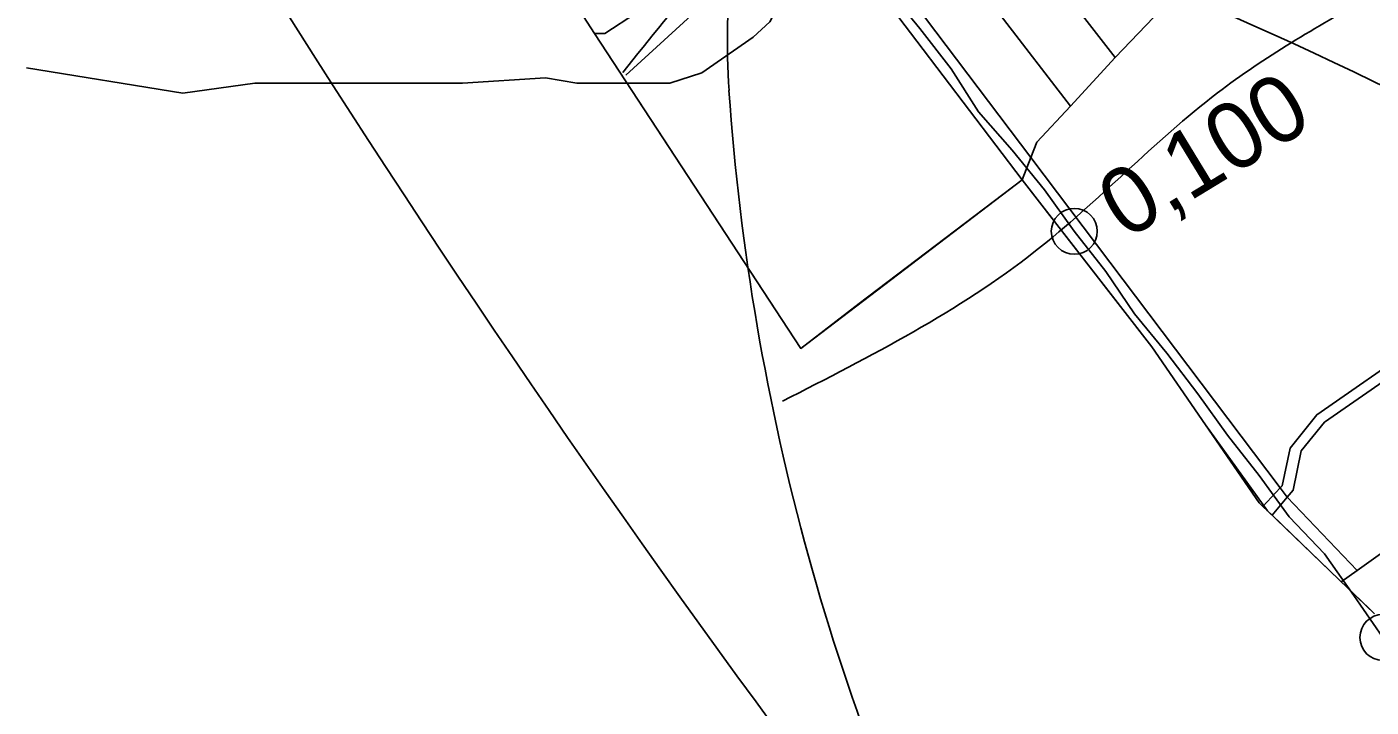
# Model space of a CAD drawing. Extents: x -510989 to -501240, y -1184665 to -1176089.
# Drawn here: x -505400.5 to -505137.3, y -1182850.2 to -1182717 of the extents above; entities that cross this region are included whole.
import ezdxf

# ---------------------------------------------------------------- set-up
doc = ezdxf.new("R2010")
doc.units = 0
for name, color, linetype in [('NAVRH_revitalizace_toku', 7, 'Continuous'), ('NAVRH_rozvodnice', 7, 'Continuous'), ('orna_puda', 7, 'Continuous'), ('ostatni_plocha_x_silnice', 7, 'Continuous'), ('popis', 7, 'Continuous'), ('STAV_povodi', 7, 'Continuous'), ('STAV_zaplavove_uzemi', 7, 'Continuous'), ('trasovani_toku', 7, 'Continuous'), ('trvaly_travni_porost', 7, 'Continuous'), ('vodni_plocha_x_vodni_tok_v_koryt_prir_n_upr', 7, 'Continuous'), ('vrstevnice_02', 7, 'Continuous')]:
    doc.layers.add(name, color=color, linetype=linetype)

msp = doc.modelspace()

# ---------------------------------------------------------------- linework, layer by layer
at = {"layer": 'NAVRH_revitalizace_toku'}
msp.add_lwpolyline([(-505283.2, -1182726.47), (-505221.54, -1182670.07), (-505202.54, -1182651.66), (-505180.34, -1182644.65), (-505164.26, -1182628.87), (-505157.25, -1182622.73), (-505143.22, -1182616.3), (-505134.75, -1182614.84), (-505111.96, -1182609.29), (-505091.21, -1182601.11), (-505056.43, -1182579.77), (-505023.12, -1182558.15), (-505007.92, -1182543.25), (-505004.12, -1182535.35), (-504999.17, -1182521.37), (-504988.56, -1182507.87), (-504967.99, -1182486.66), (-504957.7, -1182478.94), (-504947.42, -1182468.01), (-504933.59, -1182458.37), (-504921.38, -1182450.01)], dxfattribs=at)
at = {"layer": 'NAVRH_rozvodnice'}
for centre, radius, start, end in [((-503349.55, -1181451.68), 2365.2, 210.66565, 230.3961), ((-505125.66, -1182720), 137.67, 162.3818, 183.9514), ((-505444.54, -1183359.44), 702.72, 47.17982, 69.65509), ((-504801.14, -1182697.59), 462.97, 183.9514, 206.882)]:
    msp.add_arc(centre, radius, start, end, dxfattribs=at)
at = {"layer": 'orna_puda'}
for points in [[(-505231.63, -1182667.65), (-505226.84, -1182655.02), (-505192.37, -1182699.02), (-505179.82, -1182715.12), (-505187.44, -1182722.98), (-505200.69, -1182705.9)], [(-505241.82, -1182674.43), (-505231.63, -1182667.65), (-505200.69, -1182705.9), (-505187.44, -1182722.98), (-505196.15, -1182732.5), (-505209.95, -1182714.66), (-505211.47, -1182712.73)], [(-505250.53, -1182680.83), (-505241.82, -1182674.43), (-505211.47, -1182712.73), (-505209.95, -1182714.66), (-505196.15, -1182732.5), (-505202.73, -1182739.56), (-505203.93, -1182742.58), (-505222.49, -1182717.98)], [(-505156.25, -1182694.93), (-505150.23, -1182691.81), (-505144.19, -1182698.42), (-505095.58, -1182752.22), (-505092.58, -1182755.01), (-505109.05, -1182765.57), (-505128.01, -1182779.16), (-505147.95, -1182792.96), (-505153.14, -1182799.48), (-505154.69, -1182806.86), (-505155.1, -1182807.3), (-505203.93, -1182742.58), (-505202.73, -1182739.56), (-505196.15, -1182732.5), (-505187.44, -1182722.98), (-505179.82, -1182715.12), (-505171.72, -1182706.71), (-505163.37, -1182699.78)]]:
    msp.add_lwpolyline(points, close=True, dxfattribs=at)
for points in [[(-505091.34, -1182756.24), (-505146.42, -1182794.45), (-505150.98, -1182800.01), (-505152.59, -1182807.74), (-505153.74, -1182809.11), (-505155.1, -1182807.3), (-505154.69, -1182806.86), (-505153.14, -1182799.48), (-505147.95, -1182792.96), (-505128.01, -1182779.16)], [(-505135, -1182819.86), (-505140.03, -1182823.47), (-505153.74, -1182809.11), (-505152.59, -1182807.74), (-505150.98, -1182800.01), (-505146.42, -1182794.45), (-505091.34, -1182756.24)]]:
    msp.add_lwpolyline(points, dxfattribs=at)
at = {"layer": 'ostatni_plocha_x_silnice'}
msp.add_lwpolyline([(-505137.06, -1182831.56), (-505137.71, -1182830.93), (-505142.18, -1182826.63), (-505143.15, -1182825.7), (-505140.03, -1182823.47), (-505135, -1182819.86)], dxfattribs=at)
at = {"layer": 'popis'}
msp.add_lwpolyline([(-505136.66, -1182831.95), (-505143.65, -1182825.21), (-505157.59, -1182811.77), (-505169.71, -1182794.94), (-505180.22, -1182779.67), (-505192.93, -1182763.3), (-505205.65, -1182746.93), (-505248.97, -1182779.98), (-505289.32, -1182718.3), (-505291.51, -1182714.95), (-505297.03, -1182708.17), (-505302.52, -1182701.43), (-505318.05, -1182675.76), (-505333.58, -1182650.08), (-505360.57, -1182611.94), (-505382.19, -1182577), (-505390.4, -1182557.12), (-505398.6, -1182537.25), (-505408.11, -1182520.53), (-505418.12, -1182507.31), (-505446.34, -1182476.48), (-505468.66, -1182447.55)], dxfattribs=at)
at = {"layer": 'STAV_povodi'}
msp.add_arc((-503349.55, -1181451.68), 2365.2, 210.66565, 230.3961, dxfattribs=at)
at = {"layer": 'STAV_zaplavove_uzemi'}
for points in [[(-505319.13, -1182678.81), (-505278.86, -1182647.83), (-505216.92, -1182606.02), (-505167.36, -1182584.34), (-505141.03, -1182562.66), (-505106.96, -1182547.17), (-505057.41, -1182451.15), (-505009.4, -1182400.05), (-504983.07, -1182370.62), (-504989.26, -1182324.16), (-504952.1, -1182266.86), (-504922.67, -1182223.5), (-504871.57, -1182172.39), (-504862.27, -1182161.55), (-504862.27, -1182184.78), (-504874.66, -1182232.79), (-504874.66, -1182282.35), (-504862.27, -1182341.2), (-504848.34, -1182390.75), (-504852.98, -1182434.12), (-504880.86, -1182479.03), (-504888.6, -1182511.55), (-504908.73, -1182559.56), (-504924.22, -1182582.79), (-505001.65, -1182633.9), (-505054.31, -1182661.77), (-505105.41, -1182692.74), (-505137.93, -1182711.33), (-505167.36, -1182729.91), (-505202.98, -1182760.89), (-505252.54, -1182790.31)], [(-504871.86, -1182277.65), (-504898.88, -1182273.67), (-504904.45, -1182291.95), (-504901.27, -1182320.56), (-504895.7, -1182351.55), (-504897.29, -1182379.37), (-504910.01, -1182411.95), (-504910.8, -1182436.59), (-504925.11, -1182447.71), (-504944.18, -1182462.02), (-504958.49, -1182467.58), (-504959.75, -1182470.16), (-504972.25, -1182467.27), (-504984.75, -1182473.04), (-504997.25, -1182487.47), (-504997.25, -1182510.55), (-505009.75, -1182529.78), (-505029.95, -1182546.12), (-505045.33, -1182559.59), (-505069.37, -1182570.17), (-505097.26, -1182593.24), (-505115.53, -1182605.74), (-505138.61, -1182609.59), (-505147.26, -1182609.59), (-505169.38, -1182630.75), (-505190.53, -1182642.28), (-505212.65, -1182646.13), (-505220.34, -1182650.94), (-505225.15, -1182670.17), (-505247.27, -1182689.4), (-505283.81, -1182725.94)]]:
    msp.add_spline(points, degree=3, dxfattribs=at)
at = {"layer": 'trasovani_toku'}
for p, q in [((-505231.96, -1182709.55), (-505225.65, -1182717.3)), ((-505225.65, -1182717.3), (-505219.53, -1182725.21)), ((-505219.53, -1182725.21), (-505214.14, -1182733.64)), ((-505214.14, -1182733.64), (-505207.55, -1182741.16)), ((-505207.55, -1182741.16), (-505201.22, -1182748.9)), ((-505201.22, -1182748.9), (-505195.41, -1182757.04)), ((-505195.41, -1182757.04), (-505189.22, -1182764.89)), ((-505189.22, -1182764.89), (-505183.62, -1182773.18)), ((-505183.62, -1182773.18), (-505177.3, -1182780.92)), ((-505177.3, -1182780.92), (-505171.21, -1182788.85)), ((-505171.21, -1182788.85), (-505165.4, -1182796.99)), ((-505165.4, -1182796.99), (-505159.2, -1182804.84)), ((-505159.2, -1182804.84), (-505153.34, -1182812.95)), ((-505153.34, -1182812.95), (-505146.44, -1182820.19)), ((-505146.44, -1182820.19), (-505140.69, -1182828.36)), ((-505140.69, -1182828.36), (-505135.01, -1182836.59))]:
    msp.add_line(p, q, dxfattribs=at)
for centre in [(-505195.41, -1182757.04), (-505135.01, -1182836.59)]:
    msp.add_circle(centre, 4.5, dxfattribs=at)
at = {"layer": 'trvaly_travni_porost'}
msp.add_lwpolyline([(-505262.86, -1182681.25), (-505255.68, -1182681.01), (-505226.26, -1182719.78), (-505205.65, -1182746.93), (-505237.51, -1182771.18), (-505248.97, -1182779.98), (-505273.59, -1182742.35), (-505289.32, -1182718.3), (-505287.34, -1182718.32), (-505281.09, -1182714.23), (-505274.17, -1182697.18)], close=True, dxfattribs=at)
at = {"layer": 'vodni_plocha_x_vodni_tok_v_koryt_prir_n_upr'}
for points in [[(-505255.68, -1182681.01), (-505250.53, -1182680.83), (-505222.49, -1182717.98), (-505203.93, -1182742.58), (-505205.65, -1182746.93), (-505226.26, -1182719.78)], [(-505203.93, -1182742.58), (-505155.1, -1182807.3), (-505158.48, -1182810.91), (-505159.2, -1182810.21), (-505180.22, -1182779.67), (-505205.65, -1182746.93)], [(-505153.74, -1182809.11), (-505156.69, -1182812.63), (-505158.48, -1182810.91), (-505155.1, -1182807.3)], [(-505156.69, -1182812.63), (-505153.74, -1182809.11), (-505140.03, -1182823.47), (-505143.15, -1182825.7), (-505143.65, -1182825.21)]]:
    msp.add_lwpolyline(points, close=True, dxfattribs=at)
msp.add_lwpolyline([(-505281.09, -1182714.23), (-505287.34, -1182718.32), (-505289.32, -1182718.3), (-505291.51, -1182714.95)], dxfattribs=at)
at = {"layer": 'vrstevnice_02'}
msp.add_lwpolyline([(-505400.5, -1182725), (-505369.91, -1182730), (-505355.81, -1182728), (-505315.19, -1182728), (-505298.91, -1182727), (-505292.81, -1182728), (-505274.59, -1182728), (-505268.31, -1182726), (-505258.31, -1182719), (-505255, -1182716), (-505248, -1182702), (-505243.91, -1182696), (-505239.81, -1182695), (-505235.5, -1182696), (-505231.41, -1182698), (-505225.31, -1182704), (-505223.41, -1182706), (-505214.41, -1182681), (-505209.09, -1182675), (-505199.19, -1182657), (-505192.31, -1182648), (-505180, -1182638), (-505158.59, -1182630), (-505132.09, -1182614)], dxfattribs=at)

# ---------------------------------------------------------------- texts
at = {"layer": 'trasovani_toku'}
msp.add_text('0,100', height=13, rotation=31.3394, dxfattribs=at).set_placement((-505185.36, -1182758.85))

doc.saveas('drawing.dxf')
